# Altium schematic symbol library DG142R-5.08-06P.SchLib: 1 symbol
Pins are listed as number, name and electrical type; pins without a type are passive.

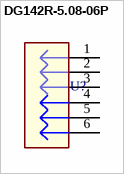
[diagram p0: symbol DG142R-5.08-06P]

## DG142R-5.08-06P
designator U?  (value not drawn)
DG129-5.0-03P-14-00AH
footprint DG142R-5.08-06P
pins: 1, 2, 3, 4, 5, 6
